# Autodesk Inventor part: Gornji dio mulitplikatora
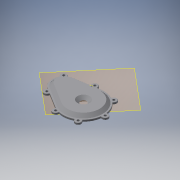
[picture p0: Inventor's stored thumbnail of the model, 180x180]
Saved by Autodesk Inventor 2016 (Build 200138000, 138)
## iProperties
Created: 2015-08
Part Number: Gornji dio mulitplikatora
Material: Generic
Document SubType Name: Modeling
Designer: stank
Density: 1 g/cm^3
Appearance: Default
Author: stank
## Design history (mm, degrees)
workplane "Work Plane1"
sketch "Sketch1"
  geometry: L1 (-33.028, 42.698)-(27.802, -9.971) reference; L2 (-79.077, -68.402)-(-90.579, 11.235) reference; L3 (-95.528, 10.521)-(-95.242, 8.541) reference; L4 (-100.047, 6.837)-(-96.088, 7.409) reference; L5 (-93.23, -12.386)-(-97.189, -12.958) reference; L6 (-92.097, -13.233)-(-84.026, -69.117) reference; L7 (-84.078, -73.704)-(-87.967, -75.12) reference; L8 (-81.127, -93.914)-(-77.237, -92.498) reference; L9 (-42.558, -124.275)-(-43.63, -128.273) reference; L10 (-24.311, -133.45)-(-23.24, -129.452) reference; L11 (22.682, -119.271)-(25.342, -122.442) reference; L12 (40.663, -109.586)-(38.003, -106.415) reference; L13 (56.003, -62.959)-(60.126, -62.599) reference; L14 (58.383, -42.675)-(54.26, -43.035) reference; L15 (31.075, -6.191)-(23.921, 0.004) reference; L16 (23.819, 1.415)-(26.437, 4.439) reference; L17 (11.317, 17.53)-(8.699, 14.506) reference; L18 (7.289, 14.405)-(-29.755, 46.478) reference; L19 (-42.165, 58.93)-(-42.534, 54.713) reference; L20 (-62.458, 56.457)-(-62.089, 60.673) reference; C1 r 4 at (-52.127, 59.802) reference; C2 r 4 at (18.877, 10.984) reference; C3 r 4 at (-98.618, -3.06) reference; C4 r 4 at (-84.547, -84.517) reference; C5 r 4 at (-33.97, -130.862) reference; C6 r 4 at (33.003, -116.014) reference; C7 r 4 at (59.255, -52.637) reference; A1 r 35 centre (-55.938, 16.238) between (-33.028, 42.698) and (-90.579, 11.235) reference; A2 r 65 centre (-14.745, -59.111) between (-79.077, -68.402) and (27.802, -9.971) reference; A3 r 40 centre (-55.938, 16.238) between (-63.271, 55.561) and (-95.528, 10.521) reference; A4 r 1 centre (-96.231, 8.398) between (-96.088, 7.409) and (-95.242, 8.541) reference; A5 r 10 centre (-98.618, -3.06) between (-100.047, 6.837) and (-97.189, -12.958) reference; A6 r 1 centre (-93.087, -13.376) between (-92.097, -13.233) and (-93.23, -12.386) reference; A7 r 70 centre (-14.745, -59.111) between (-84.026, -69.117) and (-83.438, -72.572) reference; A8 r 1 centre (-84.42, -72.764) between (-84.078, -73.704) and (-83.438, -72.572) reference; A9 r 10 centre (-84.547, -84.517) between (-87.967, -75.12) and (-81.127, -93.914) reference; A10 r 1 centre (-76.895, -93.437) between (-76.02, -92.954) and (-77.237, -92.498) reference; A11 r 70 centre (-14.745, -59.111) between (-76.02, -92.954) and (-43.119, -123.102) reference; A12 r 1 centre (-43.524, -124.016) between (-42.558, -124.275) and (-43.119, -123.102) reference; A13 r 10 centre (-33.97, -130.862) between (-43.63, -128.273) and (-24.311, -133.45) reference; A14 r 1 centre (-22.274, -129.71) between (-22.168, -128.716) and (-23.24, -129.452) reference; A15 r 70 centre (-14.745, -59.111) between (-22.168, -128.716) and (21.399, -119.057) reference; A16 r 1 centre (21.916, -119.914) between (22.682, -119.271) and (21.399, -119.057) reference; A17 r 10 centre (33.003, -116.014) between (25.342, -122.442) and (40.663, -109.586) reference; A18 r 1 centre (38.769, -105.772) between (38.015, -105.115) and (38.003, -106.415) reference; A19 r 70 centre (-14.745, -59.111) between (38.015, -105.115) and (55.092, -63.887) reference; A20 r 1 centre (56.09, -63.955) between (56.003, -62.959) and (55.092, -63.887) reference; A21 r 10 centre (59.255, -52.637) between (60.126, -62.599) and (58.383, -42.675) reference; A22 r 1 centre (54.172, -42.039) between (53.202, -42.28) and (54.26, -43.035) reference; A23 r 70 centre (-14.745, -59.111) between (53.202, -42.28) and (31.075, -6.191) reference; A24 r 1 centre (24.575, 0.76) between (23.819, 1.415) and (23.921, 0.004) reference; A25 r 10 centre (18.877, 10.984) between (26.437, 4.439) and (11.317, 17.53) reference; A26 r 1 centre (7.943, 15.161) between (7.289, 14.405) and (8.699, 14.506) reference; A27 r 40 centre (-55.938, 16.238) between (-29.755, 46.478) and (-41.889, 53.69) reference; A28 r 1 centre (-41.538, 54.626) between (-42.534, 54.713) and (-41.889, 53.69) reference; A29 r 10 centre (-52.127, 59.802) between (-42.165, 58.93) and (-62.089, 60.673) reference; A30 r 1 centre (-63.454, 56.544) between (-63.271, 55.561) and (-62.458, 56.457) reference; 1 further point
extrude "Extrusion1" new body sketch "Sketch1" distance "d0" = 6; taper "d1" = 0 deg
sketch "Sketch2"
  geometry: L1 (-42.698, -33.028)-(9.971, 27.802) reference; L2 (68.402, -79.077)-(-11.235, -90.579) reference; C1 r 13.5 at (59.111, -14.745); C2 r 10 at (59.111, -14.745) reference; A1 r 65 centre (59.111, -14.745) between (68.402, -79.077) and (9.971, 27.802) reference; A2 r 35 centre (-16.238, -55.938) between (-42.698, -33.028) and (-11.235, -90.579) reference; 1 further point
  constraints: 1 centre point, 1 coincident
  dimensions: "d24" = 27 diameter of C1
  node "Reference9"
workplane "Work Plane3"
sketch "Sketch4"
  geometry: C1 r 23.5 at (11.642, -52.082) reference; C2 r 12.5 at (11.642, -52.082) reference; C3 r 13.5 at (11.642, -52.082); C4 r 13.1 at (-59.111, -14.745) reference; C5 r 14.1 at (-59.111, -14.745)
  constraints: 2 centre point, 2 coincident
  dimensions: "d10" = 1 radial gap between concentric circles of C2 C3; "d27" = 1 radial gap between concentric circles of C5 C4
extrude "Extrusion5" join sketch "Sketch4" distance "d11" = 1; taper "d12" = 0 deg
workplane "Work Plane2"
sketch "Sketch5"
  geometry: C1 r 23.5 at (11.642, -52.082) reference; C2 r 23.5 at (-57.817, -12.389) reference; C3 r 26.5 at (11.642, -52.082); C4 r 26.5 at (-57.817, -12.389); 1 further point
  constraints: 2 centre point, 2 coincident
  dimensions: "d14" = 3 radial gap between concentric circles of C2 C4; "d15" = 3 radial gap between concentric circles of C3 C1
extrude "Extrusion6" join sketch "Sketch5" distance "d16" = 13; taper "d17" = 0 deg
fillet "Fillet3" dims "d22" = 1
extrude "Extrusion7" join sketch "Sketch2" distance "d25" = 10; taper "d26" = 0 deg
chamfer "Chamfer2" distance "d29" = 9; stored, may be unused: second distance "d30" = 2, angle "d31" = 45 deg
chamfer "Chamfer3" distance "d32" = 2; stored, may be unused: second distance "d33" = 2, angle "d34" = 45 deg
body "Solid1"
node "Reference1"
node "Reference11"
